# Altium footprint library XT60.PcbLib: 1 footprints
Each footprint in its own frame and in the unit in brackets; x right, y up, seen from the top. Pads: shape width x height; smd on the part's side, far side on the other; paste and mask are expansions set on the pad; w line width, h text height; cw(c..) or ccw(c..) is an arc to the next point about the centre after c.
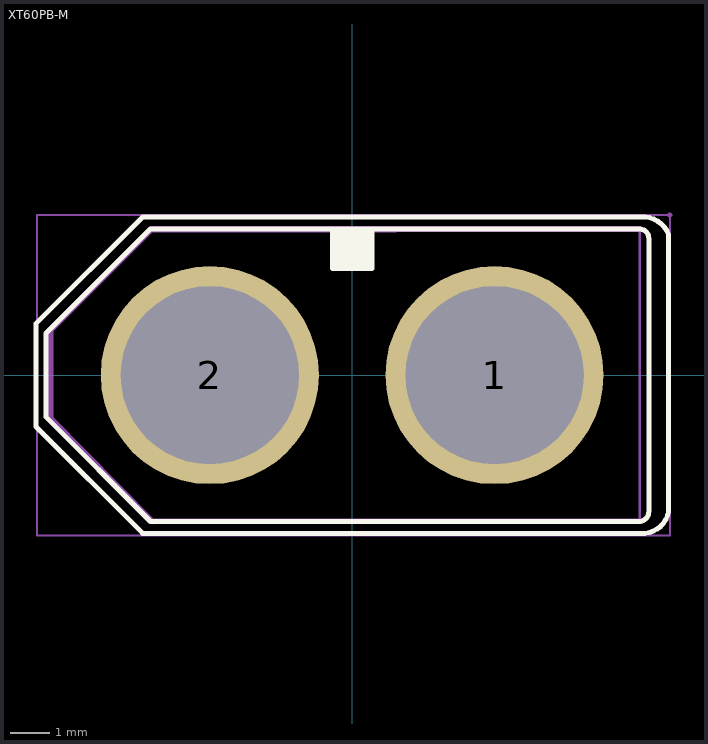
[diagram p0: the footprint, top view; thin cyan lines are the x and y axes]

## XT60PB-M [mm]
pads (2):
  round 5.516 hole 4.5 slot 4.505 at 0 deg: 1(3.6,0) 2(-3.6,0)
Top Overlay:
  lines w0.127: -0.5,3.7 -0.4,3.7 ; -0.3,2.7 -0.3,3.7 ; 0,2.7 0,3.7 ; 0.3,2.7 0.3,3.7 ; 0.5,3.7 0.4,3.7 ; 7.25,-3.701 -5.099,-3.701 -7.746,-1.052 -7.746,1.052 -5.099,3.701 -0.499,3.701 -0.499,2.7 -0.4,2.7 ; 7.25,-3.7 ccw(c7.25,-3.45) 7.5,-3.45 7.5,3.45 ccw(c7.25,3.45) 7.25,3.7 ; 7.25,3.701 0.499,3.701 0.499,2.7 0.4,2.7 ; 7.3,-4 ccw(c7.339,-3.328) 8.002,-3.444 ; 7.301,-4 -5.3,-4 -8,-1.3 -8,1.3 -5.3,4 7.301,4 cw(c7.348,3.301) 8.001,3.556 8.001,-3.444 ; -0.4,2.7 -0.4,3.7 ; -0.4,2.7 -0.299,2.7 -0.2,2.7 ; -0.4,3.7 -0.3,3.7 ; -0.3,3.7 -0.2,3.7 ; -0.2,2.7 -0.2,3.7 ; -0.2,2.7 -0.101,2.7 ; -0.2,3.7 -0.1,3.7 ; -0.1,2.7 -0.1,3.7 ; -0.101,2.7 0.001,2.7 0.1,2.7 ; -0.1,3.7 0,3.7 ; 0,3.7 0.1,3.7 ; 0.1,2.7 0.1,3.7 ; 0.1,2.7 0.199,2.7 ; 0.1,3.7 0.2,3.7 ; 0.2,2.7 0.2,3.7 ; 0.199,2.7 0.301,2.7 0.4,2.7 ; 0.2,3.7 0.3,3.7 ; 0.3,3.7 0.4,3.7 ; 0.4,2.7 0.4,3.7
Mechanical 6:
  region: -7.56,1.11 -7.56,-1.07 -7.77,-1.07 -7.77,1.11
  region: 7.29,3.63 7.29,-3.63 7.25,-3.63 7.25,3.63
  region: -5.03,-3.77 -7.772,-1.07 -7.56,-1.07 -5.03,-3.63
  region: -5.07,3.77 -5.11,3.77 -7.77,1.11 -7.59,1.11 -7.56,1.11 -5.07,3.6
  region: -5.07,3.6 -5.07,3.77 7.29,3.77 7.29,3.63
  region: -5.03,-3.77 -5.03,-3.63 7.29,-3.63 7.29,-3.74
  region: -0.508,3.683 -0.508,2.667 0.508,2.667 0.508,3.683
Mechanical 15:
  region: 5.6,0 5.6,0.197 5.523,0.583 5.372,0.947 5.153,1.275 4.875,1.553 4.547,1.772 4.183,1.923 3.797,2 3.403,2 3.017,1.923 2.653,1.772 2.325,1.553 2.046,1.275 1.828,0.947 1.677,0.583 1.6,0.197 1.6,0 1.6,-0.197 1.677,-0.583 1.828,-0.947 2.046,-1.275 2.325,-1.553 2.653,-1.772 3.017,-1.923 3.403,-2 3.797,-2 4.183,-1.923 4.547,-1.772 4.875,-1.553 5.153,-1.275 5.372,-0.947 5.523,-0.583 5.6,-0.197 5.6,0
  region: -1.6,0 -1.6,0.197 -1.677,0.583 -1.828,0.947 -2.046,1.275 -2.325,1.553 -2.653,1.772 -3.017,1.923 -3.403,2 -3.797,2 -4.183,1.923 -4.547,1.772 -4.875,1.553 -5.153,1.275 -5.372,0.947 -5.523,0.583 -5.6,0.197 -5.6,0 -5.6,-0.197 -5.523,-0.583 -5.372,-0.947 -5.153,-1.275 -4.875,-1.553 -4.547,-1.772 -4.183,-1.923 -3.797,-2 -3.403,-2 -3.017,-1.923 -2.653,-1.772 -2.325,-1.553 -2.046,-1.275 -1.828,-0.947 -1.677,-0.583 -1.6,-0.197 -1.6,0
  region: 8.09,4.05 8.089,4.075 8.054,4.109 8.005,4.109 7.971,4.075 7.97,4.05 7.971,4.026 8.005,3.991 8.054,3.991 8.089,4.026 8.09,4.05
  lines w0.051: -7.97,-4.05 8.03,-4.05 8.03,4.05 -7.97,4.05 -7.97,-4.05
3D body "CONN-TH_XT60PB-M.step": height 16, standoff -4, extent -8.034,-4.034 7.966,4.067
